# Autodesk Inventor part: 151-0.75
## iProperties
Created: 2007-06
Part Number: 151-0.75
Document SubType Name: Modeling
Designer: btaylor
Density: 1 g/cm^3
Author: btaylor
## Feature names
1. Sweep1
2. Extrusion1
3. Extrusion2
4. Extrusion3
5. Extrusion4
6. Sweep5
7. Fillet1
8. Fillet2
9. Fillet3
10. Fillet4
11. Chamfer1
12. Chamfer2
13. Fillet5
14. Fillet6
